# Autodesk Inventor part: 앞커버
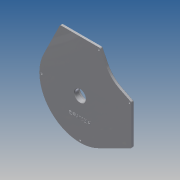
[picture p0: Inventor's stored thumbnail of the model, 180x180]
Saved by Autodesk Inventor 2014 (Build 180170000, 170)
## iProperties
Created: 2017-05
Part Number: 앞커버
Material: 알루미늄 6061
Document SubType Name: Modeling
Designer: mduedu
Density: 2.71 g/cm^3
Mass: 321.629 g
Surface Area: 500.043 cm^2
Volume: 118.682 cm^3
Appearance: 알루미늄 - 평지
Author: mduedu
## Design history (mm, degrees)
sketch "스케치1"
  geometry: L1 (-71.801, 35.28)-(-40, 100); L2 (-40, 100)-(40, 100); L3 (40, 100)-(52.248, 75.073); L4 (35.28, 71.801)-(59.768, 59.768); L5 (100, 40)-(100, -40); L6 (100, -40)-(35.28, -71.801); L7 (75.073, 52.248)-(100, 40); L8 (59.768, 59.768)-(71.801, 35.28); L9 (33.075, -67.313)-(95, -36.886); L10 (95, -36.886)-(95, 36.886); L11 (95, 36.886)-(72.868, 47.76); L12 (47.76, 72.868)-(36.886, 95); L13 (36.886, 95)-(-36.886, 95); L14 (-36.886, 95)-(-67.313, 33.075); A1 r 80 centre (0, 0) between (71.801, 35.28) and (-71.801, 35.28); A2 r 80 centre (0, 0) between (35.28, -71.801) and (71.801, 35.28); A3 r 80 centre (0, 0) between (-71.801, 35.28) and (35.28, -71.801); A4 r 50 centre (97.123, 97.123) between (52.248, 75.073) and (75.073, 52.248); A5 r 55 centre (97.123, 97.123) between (47.76, 72.868) and (72.868, 47.76); A6 r 75 centre (0, 0) between (-67.313, 33.075) and (33.075, -67.313); 3 further points
  constraints: 29 end point, 15 tangent, 14 point on circle, 6 centre point, 2 midpoint, 2 perpendicular, 2 point on line, 1 coincident, 1 horizontal, 1 horizontal alignment, 1 vertical alignment, 6 other
  dimensions: "d0" = 160 diameter of A1; "d1" = 100 distance from line of L2 point (0, 0); "d2" = 100 distance from line of L5 point (0, 0); "d3" = 80 distance of L1.end L2.end; "d4" = 80 distance of L5.start L5.end; "d5" = 50 radius of A4; "d6" = 5 distance between parallel lines of L13 L2
extrude "돌출1" new body sketch "스케치1" distance "d7" = 5; taper "d8" = 0 deg
fillet "모깎기1" dims "d9" = 3
sketch "스케치2"
  geometry: C1 r 22 at (0, 0); 1 further point
  constraints: 1 centre point, 1 coincident
  dimensions: "d10" = 44 diameter of C1
extrude "돌출2" join sketch "스케치2" distance "d11" = 12.5; taper "d12" = 0 deg
sketch "스케치3"
  geometry: C1 r 18.5 at (0, 0); 1 further point
  constraints: 1 centre point, 1 coincident
  dimensions: "d13" = 37 diameter of C1
extrude "돌출3" cut sketch "스케치3" distance "d14" = 9; taper "d15" = 0 deg
hole "구멍1" diameter "d18" = 20; stored, may be unused: countersink angle "d22" = 90 deg, drill point angle "d24" = 118 deg; dims "d16" = 10, "d17" = 10, "d19" = 6, "d20" = 4, "d21" = 2, "d23" = 8
fillet "모깎기2" dims "d25" = 3
chamfer "모따기1" distance "d27" = 1; stored, may be unused: second distance "d28" = 2, angle "d29" = 45 deg
sketch "스케치4"
  geometry: 2 further points
  constraints: 1 vertical alignment, 1 other
  dimensions: "d30" = 35 distance of point (0, -35) point (0, 0)
feature "엠보싱1" sketch "스케치4" dims "d31" = 0.5, "d32" = 0
chamfer "모따기2" distance "d33" = 1; stored, may be unused: second distance "d34" = 2, angle "d35" = 45 deg
chamfer "모따기3" distance "d36" = 1; stored, may be unused: second distance "d37" = 2, angle "d38" = 45 deg
sketch "스케치5"
  geometry: L1 (18.989, -35.003)-(17.659, -35.003) reference; L2 (17.659, -35.003)-(17.659, -34.623) reference; L3 (17.659, -34.623)-(18.989, -34.623) reference; L4 (18.989, -34.623)-(18.989, -32.045) reference; L5 (18.989, -32.045)-(19.315, -32.045) reference; L6 (19.45, -32.31)-(19.45, -37.982) reference; L7 (19.45, -37.982)-(18.989, -37.982) reference; L8 (18.989, -37.982)-(18.989, -35.003) reference; L9 (-13.942, -34.352)-(-13.942, -34.746) reference; L10 (-13.942, -34.746)-(-15.061, -34.746) reference; L11 (-15.061, -34.746)-(-15.061, -36.489) reference; L12 (-15.061, -36.489)-(-15.536, -36.489) reference; L13 (-15.536, -36.489)-(-15.536, -31.998) reference; L14 (-15.536, -31.998)-(-15.231, -31.998) reference; L15 (-15.061, -32.263)-(-15.061, -34.352) reference; L16 (-15.061, -34.352)-(-13.942, -34.352) reference; L17 (-14.844, -37.439)-(-14.844, -37.819) reference; L18 (-14.844, -37.819)-(-19.193, -37.819) reference; L19 (-19.193, -37.819)-(-19.193, -36.191) reference; L20 (-19.193, -36.191)-(-18.84, -36.191) reference; L21 (-18.731, -36.408)-(-18.731, -37.439) reference; L22 (-18.731, -37.439)-(-14.844, -37.439) reference; L23 (-17.374, -32.575)-(-18.853, -32.575) reference; L24 (-18.853, -32.575)-(-18.853, -32.222) reference; L25 (-18.853, -32.222)-(-17.374, -32.222) reference; L26 (-17.374, -32.222)-(-17.374, -32.575) reference; L27 (-20.047, -33.382)-(-20.047, -33.029) reference; L28 (-20.047, -33.029)-(-16.282, -33.029) reference; L29 (-16.282, -33.029)-(-16.282, -33.382) reference; L30 (-16.282, -33.382)-(-20.047, -33.382) reference; L31 (-2.917, -37.615)-(-3.474, -36.089) reference; L32 (-3.474, -36.089)-(-5.726, -36.089) reference; L33 (-5.726, -36.089)-(-6.296, -37.615) reference; L34 (-6.296, -37.615)-(-6.777, -37.615) reference; L35 (-6.777, -37.615)-(-4.878, -32.615) reference; L36 (-4.878, -32.615)-(-4.335, -32.615) reference; L37 (-4.335, -32.615)-(-2.436, -37.615) reference; L38 (-2.436, -37.615)-(-2.917, -37.615) reference; L39 (-4.613, -33.104)-(-5.57, -35.675) reference; L40 (-5.57, -35.675)-(-3.636, -35.675) reference; L41 (-3.636, -35.675)-(-4.613, -33.104) reference; L42 (-10.095, -35.851)-(-8.284, -35.851) reference; L43 (-8.284, -35.851)-(-8.284, -37.975) reference; L44 (-8.284, -37.975)-(-8.745, -37.975) reference; L45 (-8.745, -37.975)-(-8.745, -36.225) reference; L46 (-8.745, -36.225)-(-12.578, -36.225) reference; L47 (-12.578, -36.225)-(-12.578, -35.851) reference; L48 (-12.578, -35.851)-(-10.55, -35.851) reference; L49 (-10.55, -35.851)-(-10.55, -34.63) reference; L50 (-10.55, -34.63)-(-13.311, -34.63) reference; L51 (-13.311, -34.63)-(-13.311, -34.257) reference; L52 (-13.311, -34.257)-(-8.942, -34.257) reference; L53 (-8.657, -32.588)-(-12.463, -32.588) reference; L54 (-12.463, -32.588)-(-12.463, -32.208) reference; L55 (-12.463, -32.208)-(-8.175, -32.208) reference; L56 (-8.446, -34.257)-(-7.307, -34.257) reference; L57 (-7.307, -34.257)-(-7.307, -34.63) reference; L58 (-7.307, -34.63)-(-10.095, -34.63) reference; L59 (-10.095, -34.63)-(-10.095, -35.851) reference; L60 (1.526, -32.615)-(1.526, -33.029) reference; L61 (1.526, -33.029)-(-0.034, -33.029) reference; L62 (-0.034, -33.029)-(-0.034, -37.615) reference; L63 (-0.034, -37.615)-(-0.488, -37.615) reference; L64 (-0.488, -37.615)-(-0.488, -33.029) reference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; C1 r 11 at (0, 0) reference; C2 r 4 at (-71, 0); C3 r 4 at (0, -71); C4 r 4 at (91, 34.394); C5 r 4 at (34.394, 91); A1 r 75 centre (0, 0) between (-67.313, 33.075) and (33.075, -67.313) reference; A2 r 3 centre (-35.017, 92) between (-35.017, 95) and (-37.71, 93.323) reference; A3 r 3 centre (35.017, 92) between (37.71, 93.323) and (35.017, 95) reference; A4 r 55 centre (97.123, 97.123) between (47.76, 72.868) and (72.868, 47.76) reference; A5 r 3 centre (92, 35.017) between (95, 35.017) and (93.323, 37.71) reference; A6 r 3 centre (92, -35.017) between (93.323, -37.71) and (95, -35.017) reference; A7 r 75 centre (0, 0) between (-67.313, 33.075) and (33.075, -67.313) reference; 66 further points
  constraints: 6 tangent, 4 centre point, 4 coincident, 3 equal radius, 1 horizontal alignment, 1 vertical alignment, 76 other
  dimensions: "d39" = 8 diameter of C2
  node "절단 모서리 투영1"
sketch "스케치6"
  geometry: 4 further points
  constraints: 4 other
hole "구멍2" sketch "스케치6" at (0, -71), (91, 34.394), (34.394, 91), (-71, 0) diameter "d40" = 3.4; stored, may be unused: countersink angle "d44" = 90 deg, drill point angle "d46" = 0 deg; dims "d41" = 6, "d42" = 4, "d43" = 2, "d45" = 8
node "솔리드1"
